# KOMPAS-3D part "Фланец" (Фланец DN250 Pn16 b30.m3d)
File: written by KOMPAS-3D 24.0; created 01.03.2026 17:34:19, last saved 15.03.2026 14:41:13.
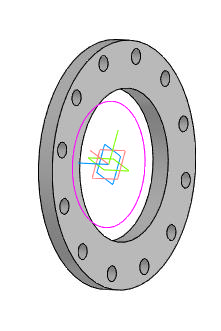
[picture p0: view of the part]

Document properties: Автор: R2D2; Полное имя файла: E:\Работа\Зайцев\GVWR2626M-2W-F-S Задвижка клиновая с выдвижным штоком DN.ru Ду50-300 Ру16\DN250\исходные материалы\Фланец DN250 Pn16 b30.m3d

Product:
- Part/product: Фланец
    Масса: 16.336215
    additional columns: Типовые

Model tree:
1. Эскиз:2
2. Элемент вращения:1
     Угол 1 = 360
3. Эскиз:3  (with: Грань.Элемент вращения:1)
4. Элемент выдавливания:2
     Расстояние 2 = 27
5. Массив по концентрической сетке:1  (with: Элемент выдавливания:2, Эскиз:3, Грань.Элемент вращения:1)  (12 pattern instances)
     Шаг 2 = 360
6. Эскиз:4  (with: Грань.Элемент вращения:1)
7. Элемент выдавливания:3
     Расстояние 2 = 4

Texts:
  Линейный размер с обрывом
